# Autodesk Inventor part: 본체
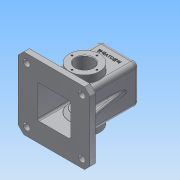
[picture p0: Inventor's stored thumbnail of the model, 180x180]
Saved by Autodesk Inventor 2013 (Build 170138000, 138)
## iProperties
Created: 2016-02
Part Number: 본체
Material: 알루미늄 6061
Document SubType Name: Modeling
Designer: Administrator
Density: 2.71 g/cm^3
Mass: 932.819 g
Surface Area: 1043.33 cm^2
Volume: 344.214 cm^3
Author: Administrator
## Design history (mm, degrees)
sketch "스케치1"
  geometry: L1 (-60, -35)-(60, -35); L2 (60, -35)-(60, 35); L3 (60, 35)-(-60, 35); L4 (-60, 35)-(-60, -35); L5 (-60, -35)-(60, 35); L6 (60, -35)-(-60, 35); 1 further point
  constraints: 12 end point, 2 midpoint, 2 parallel, 1 horizontal, 1 perpendicular
  dimensions: "d0" = 120 distance of L3.end L2.end; "d1" = 70 distance of L2.end L1.end
extrude "돌출1" new body sketch "스케치1" stored distance "d2" = 70; taper "d3" = 0 deg
sketch "스케치2"
  geometry: L1 (-50, 65)-(-60, 65); L2 (-60, 65)-(-60, -65); L3 (-60, -65)-(-50, -65); L4 (-50, -65)-(-50, 65); L5 (-60, -35)-(-60, 35) reference; 2 further points
  constraints: 8 end point, 2 midpoint, 2 parallel, 1 horizontal, 1 perpendicular
  dimensions: "d4" = 10 distance of L3.end L2.end; "d5" = 130 distance of L2.end L1.end
extrude "돌출2" join sketch "스케치2" stored distance "d6" = 130; taper "d7" = 0 deg
feature "쉘1" dims "d23" = 10, "d24" = 5
sketch "스케치3"
  geometry: L1 (35, -50)-(-35, -50) reference; L2 (-35, 60)-(-35, -50) reference; L3 (-35, 60)-(35, 60) reference; L4 (35, -50)-(35, 60) reference; L5 (-65, -50)-(65, -50) reference; L6 (65, -60)-(65, -50) reference; L7 (-65, -60)-(65, -60) reference; L8 (-65, -50)-(-65, -60) reference; L9 (50, -50)-(35, 35.069); L10 (65, -50)-(65, 24.453); 1 further point
  constraints: 4 end point, 2 point on line, 1 parallel
  dimensions: "d8" = 15 distance of L5.end L9.start; "d9" = 10 deg angle of L10 L9
feature "리브1" sketch "스케치3" dims "d10" = 1, "d11" = 10, "d12" = 0, "d13" = 0, "d14" = 1, "d15" = 1
sketch "스케치4"
  geometry: L1 (70, 0)-(70, -110) reference; L2 (5, -120)-(65, -120) reference; L3 (70, -110)-(0, -110) reference; L4 (0, 0)-(0, -110) reference; L5 (70, 0)-(0, 0) reference; L6 (70, -110)-(70, 0) reference; C1 r 27.5 at (35, -65)
  constraints: 1 centre point
  dimensions: "d16" = 55 diameter of C1; "d71" = 55 distance from line of C1.centre L2; "d72" = 35 distance from line of L1 C1.centre
extrude "돌출3" join sketch "스케치4" distance "d17" = 13; taper "d18" = 0 deg
sketch "스케치5"
  geometry: C1 r 20 at (35, -35); 1 further point
  constraints: 1 centre point, 1 coincident
  dimensions: "d19" = 40 diameter of C1
extrude "돌출4" join sketch "스케치5" distance "d20" = 10; taper "d21" = -10 deg
fillet "모깎기1" dims "d22" = 3
sketch "스케치6"
  geometry: L1 (60, 0)-(0, 0) reference; L2 (60, 0)-(60, 115) reference; C1 r 27.637 at (30, 55)
  constraints: 1 centre point
  dimensions: "d74" = 55 distance from line of L1 C1.centre; "d75" = 55.27458 diameter of C1; "d76" = 30 distance from line of L2 C1.centre
extrude "돌출5" join sketch "스케치6" distance "d26" = 7; taper "d27" = -45 deg
sketch "스케치7"
  geometry: C1 r 27.5 at (0, 0) reference; C2 r 16 at (0, 0)
  constraints: 1 centre point, 1 coincident
  dimensions: "d28" = 32 diameter of C2
extrude "돌출6" cut sketch "스케치7" stored distance "d29" = 7; taper "d30" = 0 deg
sketch "스케치8"
  geometry: C1 r 18.237 at (0, 0) reference; C2 r 14 at (0, 0)
  constraints: 1 centre point, 1 coincident
  dimensions: "d31" = 28 diameter of C2
extrude "돌출7" cut sketch "스케치8" distance "d32" = 4; taper "d33" = 0 deg
sketch "스케치9"
  geometry: C1 r 14 at (0, 0) reference; C2 r 10.5 at (0, 0)
  constraints: 1 centre point, 1 coincident
  dimensions: "d34" = 21 diameter of C2
extrude "돌출8" cut sketch "스케치9" stored distance "d35" = 4; taper "d36" = 0 deg
sketch "스케치10"
  geometry: C1 r 16 at (0, 0) reference; 1 further point
  constraints: 1 vertical alignment
  dimensions: "d37" = 22.5 distance of point (0, 22.5) C1.centre
hole "구멍1" sketch "스케치10" at (0, 22.5) diameter "d38" = 3.242; stored, may be unused: countersink angle "d42" = 90 deg, drill point angle "d44" = 118 deg; dims "d39" = 8, "d40" = 4, "d41" = 2, "d43" = 10
sketch "스케치11"
  geometry: L1 (0, 0)-(130, 0) reference; C1 r 6 at (15, -15); 1 further point
  constraints: 1 centre point
  dimensions: "d48" = 12 diameter of C1; "d49" = 50 horizontal distance of point (65, -65) C1.centre; "d50" = 15 distance from line of L1 C1.centre
extrude "돌출9" cut sketch "스케치11" stored distance "d51" = 4; taper "d52" = 0 deg
chamfer "모따기1" distance "d53" = 10; stored, may be unused: second distance "d54" = 2, angle "d55" = 45 deg
fillet "모깎기2" dims "d56" = 8
fillet "모깎기3" dims "d57" = 0.5
chamfer "모따기2" distance "d58" = 1; stored, may be unused: second distance "d59" = 2, angle "d60" = 45 deg
fillet "모깎기4" dims "d61" = 3
fillet "모깎기5" dims "d62" = 3
fillet "모깎기6" dims "d63" = 3
fillet "모깎기7" dims "d64" = 3
fillet "모깎기8" dims "d65" = 3
fillet "모깎기9" dims "d66" = 8
sketch "스케치12"
  geometry: L1 (35, -42)-(35, 57) reference; L2 (-18.237, 75)-(18.237, 75) reference; 1 further point
  constraints: 1 other
  dimensions: "d67" = 35 distance from line of L1 point (0, 45); "d68" = 30 distance from line of L2 point (0, 45)
feature "엠보싱1" sketch "스케치12" dims "d69" = 0.5, "d70" = 0
fillet "모깎기10" dims "d73" = 0.5
node "솔리드1"
mirror "대칭1"
mirror "대칭2"
mirror "대칭3"
pattern_circular "원형 패턴1" dims angle "d46" = 360 deg
mirror "대칭4"
mirror "대칭5"
mirror "대칭6"
node "투영된 루프1"
node "투영된 루프2"
node "투영된 루프3"
